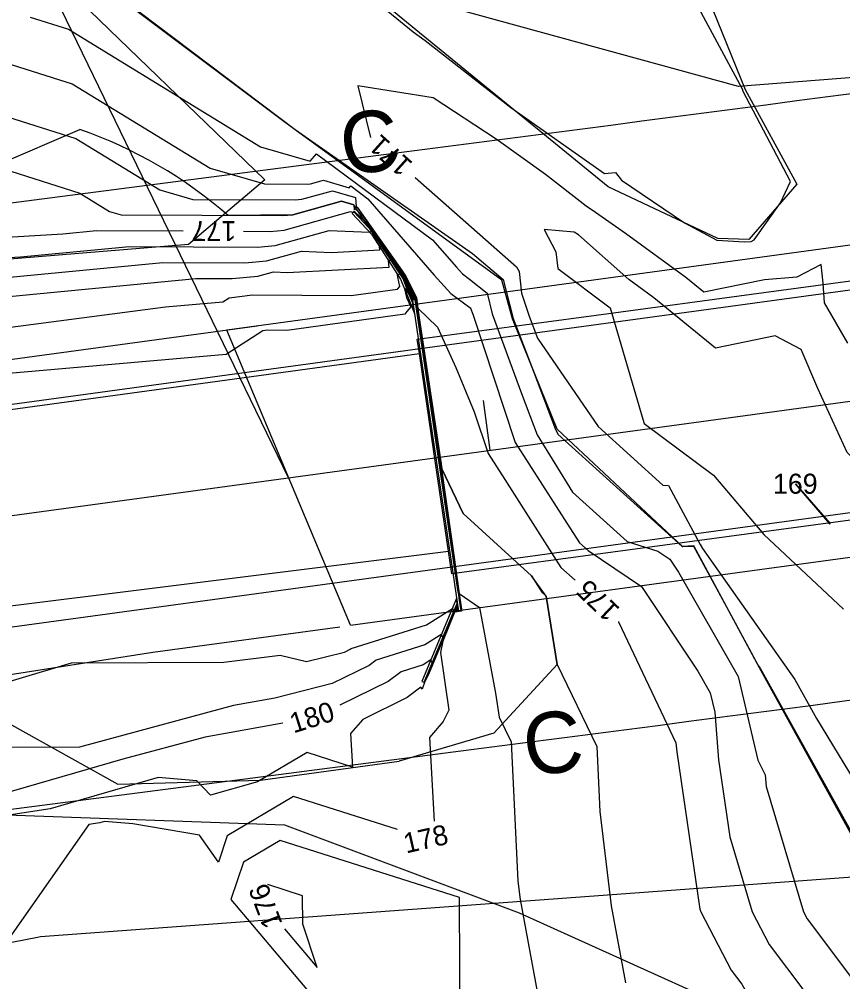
# Model space of a CAD drawing. Extents: x 2086416 to 2115205, y 575507 to 632762.
# Drawn here: x 2111475.2 to 2111557.3, y 581597.8 to 581693.8 of the extents above; entities that cross this region are included whole.
import ezdxf

# ---------------------------------------------------------------- set-up
doc = ezdxf.new("R2010")
doc.units = 0
for name, color, linetype in [('DTM Contours Major', 7, 'Continuous'), ('DTM Contours Major Text', 7, 'Continuous'), ('DTM Contours Minor', 7, 'Continuous'), ('DTM Contours Minor Text', 7, 'Continuous'), ('Exist Hydro Stream or Body of Water', 7, 'Continuous'), ('Exist Hydrographic FEMA Cross Section', 7, 'Continuous'), ('Exist Right of Way Line', 7, 'Continuous'), ('Exist Roads EOP', 7, 'Continuous'), ('Exist Structure Major Bridge WW', 7, 'Continuous'), ('Exist Structure Major Deck Tunnel Box Culvert', 7, 'Continuous'), ('Exist Vegetation Woods Line', 7, 'Continuous'), ('Prop EOT', 7, 'Continuous'), ('Prop Horizontal Alignment', 7, 'Continuous'), ('Prop Horizontal Alignment Station Label', 7, 'Continuous'), ('Prop Horizontal Alignment Tick Small', 7, 'Continuous'), ('Prop Paved Shoulder', 7, 'Continuous'), ('Prop Roadway Bridge', 7, 'Continuous'), ('Prop SS Cut Line', 7, 'Continuous'), ('Prop SS Cut Text', 7, 'Continuous'), ('Prop SS Fill Line', 7, 'Continuous')]:
    doc.layers.add(name, color=color, linetype=linetype)

msp = doc.modelspace()

# ---------------------------------------------------------------- linework, layer by layer
at = {"layer": 'DTM Contours Major'}
for points in [[(2111467.154, 581686.234), (2111480.824, 581681.896), (2111489.192, 581676.776), (2111492.494, 581675.828), (2111502.699, 581675.773), (2111503.352, 581675.831), (2111506.429, 581676.686), (2111508.704, 581676.004), (2111508.773, 581675.108), (2111508.784, 581675.119), (2111508.875, 581675.036), (2111513.354, 581668.687), (2111513.757, 581668.107), (2111514.768, 581666.071), (2111514.785, 581666.034), (2111514.789, 581666.034), (2111514.946, 581664.979), (2111516.9, 581663.081), (2111518.722, 581659.055), (2111520.566, 581654.612), (2111521.942, 581650.454), (2111523.608, 581647.867), (2111529.184, 581639.091), (2111530.614, 581637.815)], [(2111563.624, 581644.535), (2111557.765, 581650.557), (2111554.83, 581656.943), (2111553.167, 581660.831), (2111550.584, 581662.207), (2111544.629, 581660.993), (2111538.463, 581666.005), (2111535.965, 581667.83), (2111530.949, 581672.288), (2111530.521, 581672.558), (2111527.53, 581672.834), (2111528.703, 581670.603), (2111528.883, 581668.916), (2111534.119, 581665.006), (2111537.381, 581653.906), (2111537.496, 581653.447), (2111544.432, 581648.303), (2111549.461, 581642.401), (2111557.401, 581634.942)], [(2111466.87, 581665.45), (2111492.781, 581667.943), (2111496.417, 581667.924), (2111498.953, 581668.15), (2111500.543, 581668.591), (2111501.91, 581668.535), (2111512.084, 581669.069), (2111512.018, 581669.692), (2111512.151, 581669.76), (2111512.231, 581669.823), (2111513.49, 581668.014), (2111513.7, 581667.591), (2111514.529, 581665.844), (2111514.698, 581665.87), (2111515.075, 581663.328), (2111515.596, 581659.884), (2111518.365, 581641.142), (2111518.823, 581637.868), (2111519.166, 581635.474), (2111519.272, 581634.752), (2111519.14, 581634.732), (2111518.801, 581634.678), (2111518.738, 581635.071), (2111516.9, 581630.641), (2111516.405, 581629.626), (2111516.266, 581629.772), (2111516.238, 581629.874), (2111515.472, 581629.388), (2111513.263, 581628.698), (2111511.967, 581627.718), (2111507.15, 581625.341)], [(2111534.94, 581633.703), (2111534.951, 581633.685), (2111540.685, 581621.595), (2111540.754, 581620.704), (2111543.066, 581605.016), (2111543.152, 581604.727), (2111546.206, 581598.924), (2111547.253, 581597.529), (2111560.711, 581573.535), (2111564.818, 581569.801), (2111569.327, 581557.684), (2111570.482, 581553.108), (2111574.03, 581543.189)], [(2111501.468, 581623.557), (2111493.699, 581622.176), (2111485.498, 581619.952), (2111473.32, 581616.448), (2111470.815, 581616.065), (2111467.705, 581615.666), (2111457.917, 581614.372), (2111451.074, 581613.494), (2111428.1, 581610.449), (2111427.715, 581610.257), (2111423.838, 581609.834), (2111421.598, 581608.92), (2111416.907, 581607.541), (2111403.297, 581606.115)]]:
    msp.add_lwpolyline(points, dxfattribs=at)
at = {"layer": 'DTM Contours Minor'}
for points in [[(2111548.202, 581671.635), (2111548.494, 581671.785), (2111551.099, 581675.474), (2111552.125, 581677.605), (2111547.402, 581686.585), (2111547.314, 581686.835), (2111540.681, 581699.19), (2111538.366, 581697.96), (2111532.615, 581704.586), (2111527.172, 581711.478), (2111524.025, 581707.751), (2111520.624, 581705.975), (2111519.423, 581705.653), (2111518.28, 581706.433), (2111512.749, 581713.857), (2111506.226, 581719.408), (2111495.054, 581731.52), (2111493.494, 581731.308)], [(2111487.549, 581730.496), (2111484.48, 581730.078), (2111485.47, 581727.76), (2111493.951, 581708.988), (2111496.972, 581706.844), (2111514.48, 581692.545), (2111515.668, 581691.692), (2111524.198, 581685.007), (2111533.537, 581678.421), (2111534.653, 581678.496), (2111535.245, 581677.738), (2111541.518, 581673.497), (2111544.744, 581671.757), (2111547.518, 581671.576), (2111548.202, 581671.635)], [(2111486.148, 581695.197), (2111501.555, 581683.631), (2111502.551, 581682.906), (2111502.693, 581682.796), (2111520.383, 581670.408), (2111523.452, 581667.816), (2111524.362, 581664.197), (2111524.453, 581663.922), (2111526.096, 581659.621), (2111528.651, 581652.847), (2111528.944, 581652.371), (2111541.304, 581641.187), (2111541.341, 581641.176), (2111541.352, 581641.177), (2111542.435, 581641.236), (2111542.834, 581640.502), (2111546.363, 581633.993), (2111548.886, 581629.315), (2111549.076, 581629.046), (2111561.223, 581607.233)], [(2111368.765, 581694.561), (2111373.18, 581690.967), (2111376.213, 581688.421), (2111374.988, 581684.477), (2111374.345, 581683.964), (2111375.283, 581682.859), (2111378.114, 581684.026), (2111383.988, 581686.435), (2111393.453, 581684.581), (2111404.868, 581681.588), (2111405.004, 581681.538), (2111416.402, 581676.167), (2111417.82, 581675.764), (2111421.041, 581675.098), (2111426.984, 581674.836), (2111450.574, 581672.799), (2111451.554, 581672.806), (2111457.455, 581672.204), (2111464.428, 581672.63), (2111469.437, 581671.797), (2111479.516, 581672.403), (2111482.882, 581672.727), (2111491.534, 581672.68)], [(2111476.241, 581694.01), (2111480.077, 581692.793), (2111499.229, 581681.074), (2111504.206, 581679.645), (2111504.81, 581680.373), (2111516.403, 581671.803), (2111518.792, 581669.045), (2111519.393, 581668.38), (2111520.086, 581667.875), (2111521.845, 581666.467), (2111522.333, 581664.419), (2111525.28, 581656.47), (2111526.841, 581652.331), (2111530.35, 581646.62), (2111535.812, 581641.677), (2111538.872, 581640.719), (2111540.061, 581639.915), (2111540.925, 581638.611), (2111546.88, 581628.212), (2111548.864, 581619.855), (2111549.576, 581618.418), (2111549.677, 581617.246), (2111553.4, 581604.739), (2111553.764, 581604.049), (2111566.508, 581587.068)], [(2111471.697, 581690.122), (2111480.45, 581687.344), (2111494.211, 581678.925), (2111499.639, 581677.366), (2111503.956, 581677.343), (2111504.232, 581677.368), (2111505.534, 581677.729), (2111508.072, 581676.968), (2111508.234, 581677.164), (2111509.952, 581675.894), (2111516.555, 581668.27), (2111518.215, 581666.433), (2111520.131, 581665.036), (2111520.169, 581665.006), (2111520.179, 581664.962), (2111520.404, 581664.357), (2111524.641, 581651.557), (2111530.11, 581643.065), (2111531.071, 581641.554), (2111531.919, 581640.797), (2111537.24, 581637.201), (2111542.85, 581628.732), (2111544.087, 581626.573), (2111544.545, 581624.642), (2111544.913, 581619.908), (2111546.045, 581612.228), (2111548.276, 581604.733), (2111549.985, 581601.487), (2111557.086, 581592.024)], [(2111557.832, 581661.464), (2111555.517, 581665.512), (2111555.366, 581667.475), (2111555.158, 581669.318), (2111552.728, 581668.071), (2111549.514, 581667.794), (2111543.479, 581666.564), (2111541.674, 581668.031), (2111535.656, 581672.428), (2111532.643, 581674.521), (2111531.716, 581675.137), (2111527.674, 581678.306), (2111522.747, 581681.842), (2111516.457, 581685.95), (2111508.951, 581687.161), (2111510.218, 581682.003)], [(2111474.313, 581678.633), (2111481.198, 581676.448), (2111484.174, 581674.627), (2111485.348, 581674.29), (2111501.443, 581674.203), (2111502.472, 581674.295), (2111507.325, 581675.643), (2111508.552, 581675.275), (2111508.589, 581674.792), (2111508.679, 581674.876), (2111509.4, 581674.214), (2111512.43, 581669.92), (2111513.704, 581668.089), (2111514.554, 581666.375), (2111514.734, 581665.996), (2111514.771, 581666.001), (2111515.788, 581659.146), (2111517.192, 581649.853), (2111517.219, 581649.672), (2111517.321, 581648.942), (2111519.439, 581644.481), (2111526.269, 581638.248), (2111527.298, 581636.629), (2111527.742, 581636.232), (2111528.825, 581629.405), (2111532.774, 581621.227), (2111533.089, 581614.752), (2111534.221, 581605.332), (2111535.648, 581597.663)], [(2111514.671, 581678.008), (2111524.783, 581669.107), (2111525.034, 581668.631), (2111525.265, 581666.455), (2111526.022, 581664.168), (2111526.859, 581661.975), (2111532.924, 581653.146), (2111539.358, 581647.32), (2111539.946, 581647.287), (2111543.107, 581641.379), (2111543.325, 581640.975), (2111552.535, 581627.92), (2111554.709, 581624.016), (2111564.464, 581607.913)], [(2111497.534, 581672.648), (2111500.186, 581672.634), (2111501.592, 581672.759), (2111508.221, 581674.6), (2111508.4, 581674.547), (2111508.405, 581674.476), (2111508.575, 581674.633), (2111509.925, 581673.393), (2111511.505, 581671.153), (2111513.65, 581668.07), (2111514.341, 581666.679), (2111514.683, 581665.958), (2111514.753, 581665.969), (2111515.61, 581660.191), (2111516.793, 581652.361), (2111517.506, 581647.539), (2111518.546, 581640.1), (2111519.06, 581636.514), (2111521.067, 581635.109), (2111522.669, 581626.555), (2111523.048, 581624.166), (2111524.233, 581621.711), (2111524.91, 581607.809), (2111525.132, 581605.961), (2111528.046, 581590.305)], [(2111464.732, 581669.45), (2111475.3, 581670.085), (2111486.182, 581671.132), (2111498.93, 581671.064), (2111500.713, 581671.222), (2111506.079, 581672.713), (2111510.111, 581672.547), (2111510.129, 581672.563), (2111510.308, 581672.702), (2111510.451, 581672.571), (2111510.581, 581672.386), (2111513.597, 581668.051), (2111514.127, 581666.983), (2111514.631, 581665.92), (2111514.734, 581665.936), (2111515.431, 581661.237), (2111516.394, 581654.868), (2111517.792, 581645.407), (2111518.638, 581639.356), (2111519.272, 581634.932), (2111519.301, 581634.737), (2111519.265, 581634.732), (2111518.641, 581634.633), (2111518.631, 581634.695), (2111517.409, 581631.75), (2111517.204, 581630.599), (2111518.04, 581624.855), (2111517.471, 581623.738), (2111516.08, 581622.135), (2111516.553, 581613.779)], [(2111471.085, 581667.768), (2111489.481, 581669.538), (2111497.673, 581669.494), (2111499.833, 581669.686), (2111503.311, 581670.652), (2111506.303, 581670.529), (2111511.15, 581670.783), (2111511.119, 581671.08), (2111511.182, 581671.113), (2111511.324, 581671.223), (2111513.543, 581668.032), (2111513.913, 581667.287), (2111514.58, 581665.882), (2111514.716, 581665.903), (2111515.253, 581662.283), (2111515.995, 581657.376), (2111518.079, 581643.275), (2111518.731, 581638.612), (2111519.219, 581635.203), (2111519.286, 581634.745), (2111519.203, 581634.732), (2111518.721, 581634.656), (2111518.684, 581634.883), (2111516.064, 581628.567), (2111515.605, 581627.625), (2111515.364, 581626.964), (2111515.221, 581627.138), (2111513.863, 581626.111), (2111509.449, 581623.933), (2111508.219, 581622.515), (2111508.407, 581619.183), (2111503.877, 581620.626), (2111498.95, 581617.702), (2111494.253, 581616.382), (2111492.88, 581617.804), (2111489.025, 581618.122), (2111478.259, 581615.024), (2111471.081, 581613.927)], [(2111470.971, 581662.653), (2111489.767, 581665.106), (2111495.482, 581665.607), (2111496.094, 581666.005), (2111498.446, 581666.298), (2111508.265, 581666.219), (2111512.889, 581666.862), (2111513.119, 581667.125), (2111512.943, 581668.065), (2111512.918, 581668.303), (2111513.12, 581668.408), (2111513.139, 581668.423), (2111513.437, 581667.995), (2111513.486, 581667.895), (2111514.477, 581665.806), (2111514.68, 581665.837), (2111514.897, 581664.374), (2111515.196, 581662.392), (2111518.652, 581639.01), (2111518.916, 581637.124), (2111519.113, 581635.746), (2111519.258, 581634.759), (2111519.078, 581634.732), (2111518.882, 581634.701), (2111518.792, 581635.26), (2111517.736, 581632.715), (2111517.451, 581632.131), (2111517.372, 581632.216), (2111517.309, 581632.44), (2111515.626, 581631.372), (2111510.771, 581629.854), (2111510.07, 581629.324), (2111506.387, 581627.507), (2111500.669, 581626.069), (2111496.529, 581625.334), (2111481.177, 581621.169), (2111473.746, 581621.131)], [(2111514.426, 581665.768), (2111514.076, 581666.505), (2111514.07, 581666.377), (2111513.681, 581666.938), (2111513.593, 581666.892), (2111513.813, 581666.05), (2111514.217, 581665.091), (2111513.834, 581664.627), (2111513.623, 581664.386), (2111501.864, 581662.752), (2111499.925, 581662.768), (2111499.461, 581662.71), (2111495.816, 581660.338), (2111473.348, 581658.369), (2111466.15, 581656.804), (2111454.207, 581653.913), (2111447.466, 581651.924), (2111445.759, 581651.927), (2111438.707, 581650.157), (2111428.197, 581645.562), (2111418.247, 581641.471)], [(2111469.917, 581626.437), (2111480.37, 581629.578), (2111495.562, 581629.657), (2111501.182, 581630.34), (2111503.81, 581629.699), (2111507.617, 581630.655), (2111508.174, 581630.93), (2111508.279, 581631.01), (2111515.78, 581633.356), (2111518.381, 581635.005), (2111518.477, 581634.659), (2111518.498, 581634.637), (2111518.572, 581634.788), (2111518.845, 581635.448), (2111518.962, 581634.724), (2111519.015, 581634.732), (2111519.244, 581634.766), (2111519.06, 581636.017), (2111519.008, 581636.38), (2111518.938, 581636.877), (2111514.797, 581664.899), (2111514.718, 581665.42), (2111514.661, 581665.804), (2111514.426, 581665.768)], [(2111552.615, 581647.454), (2111556.02, 581643.513), (2111556.038, 581643.472), (2111556.05, 581643.46), (2111556.069, 581643.416), (2111556.042, 581643.437), (2111556.022, 581643.456), (2111552.615, 581647.454)], [(2111512.897, 581612.943), (2111502.542, 581616.244), (2111495.925, 581612.318), (2111495.047, 581609.681), (2111493.145, 581612.369), (2111486.486, 581613.505), (2111483.671, 581613.737), (2111483.198, 581613.6), (2111482.119, 581613.436), (2111472.626, 581599.987), (2111469.34, 581599.165), (2111466.838, 581596.068), (2111463.884, 581593.537), (2111423.2, 581580.097), (2111421.166, 581578.021), (2111413.921, 581573.833), (2111415.71, 581582.768), (2111413.83, 581586.352), (2111407.094, 581599.119), (2111404.077, 581600.927), (2111385.483, 581590.707), (2111395.032, 581602.545), (2111389.517, 581602.876), (2111380.322, 581601.494)], [(2111519.162, 581591.916), (2111519.094, 581606.16), (2111501.206, 581611.862), (2111497.531, 581609.681), (2111496.289, 581605.952), (2111510.712, 581588.873)], [(2111504.9, 581599.184), (2111503.45, 581603.503), (2111503.436, 581606.342), (2111499.959, 581607.451)], [(2111501.645, 581603.038), (2111504.9, 581599.184)]]:
    msp.add_lwpolyline(points, dxfattribs=at)
at = {"layer": 'Exist Hydro Stream or Body of Water'}
for points in [[(2111571.775, 581696.534), (2111557.095, 581714.198), (2111551.353, 581722.025), (2111533.92, 581727.695), (2111525.554, 581727.773), (2111514.019, 581725.289), (2111507.22, 581720.091), (2111517.385, 581713.698), (2111519.528, 581705.926), (2111524.722, 581706.159), (2111528.702, 581714.798), (2111541.061, 581702.903), (2111547.599, 581686.803), (2111552.73, 581677.358), (2111547.949, 581671.835), (2111544.848, 581671.929), (2111533.907, 581677.08), (2111514.732, 581692.736), (2111494.527, 581709.365), (2111484.151, 581730.439), (2111478.633, 581743.802)], [(2111591.587, 581574.691), (2111583.513, 581582.318), (2111586.645, 581587.276), (2111586.904, 581588.764), (2111586.51, 581589.985), (2111561.568, 581606.344), (2111549.003, 581629.07), (2111542.467, 581641.26), (2111541.348, 581641.183), (2111528.816, 581652.894), (2111524.362, 581663.908), (2111523.315, 581667.748), (2111502.682, 581682.779), (2111481.94, 581698.457), (2111468.579, 581724.282), (2111462.999, 581737.482)]]:
    msp.add_lwpolyline(points, dxfattribs=at)
at = {"layer": 'Exist Hydrographic FEMA Cross Section'}
msp.add_lwpolyline([(2111658.777, 581615.589), (2111477.281, 581602.232), (2111476.99, 581602.175), (2111467.38, 581600.311), (2111457.771, 581598.441), (2111448.167, 581596.571), (2111438.557, 581594.706), (2111428.948, 581592.837), (2111419.344, 581590.967), (2111409.734, 581589.102), (2111400.125, 581587.233), (2111390.521, 581585.363), (2111380.911, 581583.498), (2111371.307, 581581.628), (2111361.698, 581579.759), (2111352.088, 581577.894)], dxfattribs=at)
at = {"layer": 'Exist Right of Way Line'}
for points in [[(2111371.804, 581662.16), (2111512.522, 581680.421)], [(2111379.525, 581602.659), (2111520.243, 581620.919)]]:
    msp.add_lwpolyline(points, dxfattribs=at)
for radius in [24756.937, 24816.937]:
    msp.add_arc((2108326.546, 606231.499), radius, 277.3939111, 277.8562149, dxfattribs=at)
at = {"layer": 'Exist Roads EOP'}
for points in [[(2111417.782, 581647.422), (2111417.782, 581647.422), (2111466.254, 581653.757), (2111515.092, 581660.442), (2111516.542, 581650.631)], [(2111419.52, 581628.553), (2111419.52, 581628.553), (2111468.663, 581634.583), (2111518.005, 581640.729), (2111516.542, 581650.631)]]:
    msp.add_lwpolyline(points, dxfattribs=at)
at = {"layer": 'Exist Structure Major Bridge WW'}
for points in [[(2111514.582, 581664.44), (2111514.435, 581665.473), (2111514.083, 581666.345), (2111513.42, 581667.989), (2111510.498, 581672.497), (2111508.557, 581674.592), (2111508.374, 581674.422), (2111510.3, 581672.343), (2111513.197, 581667.873), (2111513.851, 581666.252), (2111514.582, 581664.44)], [(2111514.655, 581665.792), (2111514.408, 581665.755), (2111518.992, 581634.732), (2111519.239, 581634.769), (2111514.655, 581665.792)], [(2111518.864, 581635.514), (2111518.791, 581635.988), (2111518.239, 581634.666), (2111515.343, 581627.732), (2111515.574, 581627.636), (2111518.47, 581634.57), (2111518.864, 581635.514)]]:
    msp.add_lwpolyline(points, dxfattribs=at)
at = {"layer": 'Exist Structure Major Deck Tunnel Box Culvert'}
msp.add_lwpolyline([(2111518.338, 581638.473), (2111518.005, 581640.729), (2111516.542, 581650.631), (2111515.092, 581660.442), (2111514.879, 581661.883), (2111532.718, 581664.281), (2111549.455, 581666.531), (2111567.238, 581668.922), (2111567.482, 581667.278), (2111568.946, 581657.382), (2111570.384, 581647.665), (2111570.703, 581645.511), (2111552.911, 581643.12), (2111536.107, 581640.862), (2111518.338, 581638.473)], dxfattribs=at)
at = {"layer": 'Exist Vegetation Woods Line'}
for points in [[(2112042.216, 581740.223), (2112007.086, 581741.227), (2111957.142, 581737.865), (2111908.66, 581731.855), (2111808.648, 581718.236), (2111760.407, 581712.702), (2111710.337, 581706.767), (2111661.65, 581697.223), (2111616.664, 581692.442), (2111575.004, 581689.288), (2111546.91, 581687.078), (2111515.04, 581695.859), (2111502.165, 581702.852), (2111491.109, 581719.623), (2111479.278, 581746.112)], [(2111452.102, 581736.219), (2111479.268, 581697.501), (2111499.678, 581677.784), (2111492.037, 581671.336), (2111416.636, 581665.128), (2111367.277, 581660.929), (2111318.174, 581654.198), (2111268.317, 581650.615), (2111220.664, 581649.448), (2111173.288, 581649.119), (2111125.979, 581651.571), (2111078.275, 581655.724), (2111059.793, 581657.645)], [(2111257.868, 581581.404), (2111333.104, 581590.969), (2111406.178, 581600.069), (2111473.936, 581614.42), (2111501.631, 581613.416), (2111525.035, 581604.65), (2111555.787, 581590.729), (2111597.414, 581531.022), (2111635.4, 581485.12), (2111692.38, 581438.808), (2111736.925, 581397.696), (2111757.961, 581379.063)]]:
    msp.add_lwpolyline(points, dxfattribs=at)
at = {"layer": 'Prop EOT'}
for p, q in [((2111430.061, 581649.328), (2112312.029, 581769.688)), ((2111433.036, 581627.53), (2112315.004, 581747.89))]:
    msp.add_line(p, q, dxfattribs=at)
at = {"layer": 'Prop Horizontal Alignment'}
msp.add_line((2111431.548, 581638.429), (2112404.465, 581771.2), dxfattribs=at)
at = {"layer": 'Prop Horizontal Alignment Station Label'}
msp.add_line((2111502.038, 581648.048), (2111433.298, 581789.658), dxfattribs=at)
at = {"layer": 'Prop Horizontal Alignment Tick Small'}
msp.add_line((2111522.151, 581650.793), (2111521.475, 581655.747), dxfattribs=at)
at = {"layer": 'Prop Paved Shoulder'}
for p, q in [((2111498.903, 581663.18), (2111463.748, 581658.382)), ((2111488.488, 581630.64), (2111507.165, 581633.188)), ((2111459.664, 581626.117), (2111488.488, 581630.64))]:
    msp.add_line(p, q, dxfattribs=at)
at = {"layer": 'Prop Roadway Bridge'}
for p, q in [((2111585.034, 581674.934), (2111495.86, 581662.765)), ((2111508.215, 581633.332), (2111495.86, 581662.765)), ((2111508.215, 581633.332), (2111597.389, 581645.501))]:
    msp.add_line(p, q, dxfattribs=at)
at = {"layer": 'Prop SS Cut Line'}
for p, q in [((2111507.325, 581675.643), (2111502.472, 581674.295)), ((2111508.552, 581675.275), (2111507.325, 581675.643)), ((2111514.771, 581666.001), (2111508.552, 581675.275)), ((2111502.472, 581674.295), (2111496.001, 581674.207)), ((2111517.321, 581648.942), (2111514.771, 581666.001)), ((2111519.439, 581644.481), (2111517.321, 581648.942)), ((2111526.269, 581638.248), (2111519.439, 581644.481)), ((2111527.742, 581636.232), (2111526.269, 581638.248)), ((2111528.825, 581629.405), (2111527.742, 581636.232)), ((2111528.825, 581629.405), (2111522.497, 581622.577)), ((2111522.497, 581622.577), (2111513.072, 581619.756))]:
    msp.add_line(p, q, dxfattribs=at)
at = {"layer": 'Prop SS Fill Line'}
for p, q in [((2111419.256, 581656.202), (2111481.214, 581682.795)), ((2111499.224, 581617.866), (2111513.072, 581619.756)), ((2111485.015, 581617.465), (2111499.224, 581617.866))]:
    msp.add_line(p, q, dxfattribs=at)
msp.add_lwpolyline([(2111474.094, 581623.547), (2111485.015, 581617.465)], dxfattribs=at)
msp.add_arc((2111466.549, 581640.517), 44.749, 48.8396, 70.86984, dxfattribs=at)

# ---------------------------------------------------------------- texts
at = {"layer": 'DTM Contours Major Text'}
for s, rotation, p in [('175', 136.44274, (2111535.191, 581634.975)), ('180', 17.43289, (2111502.531, 581622.532))]:
    msp.add_text(s, height=2, rotation=rotation, dxfattribs=at).set_placement(p)
at = {"layer": 'DTM Contours Minor Text'}
for s, rotation, p in [('171', 138.09884, (2111514.528, 581679.441)), ('177', 179.69151, (2111496.815, 581673.652)), ('178', 12.8825, (2111513.76, 581610.55)), ('176', 110.91041, (2111501.456, 581603.561))]:
    msp.add_text(s, height=2, rotation=rotation, dxfattribs=at).set_placement(p)
msp.add_text('169', height=2, dxfattribs=at).set_placement((2111550.355, 581646.454))
at = {"layer": 'Prop SS Cut Text'}
for p in [(2111507.614, 581678.163), (2111525.877, 581618.198)]:
    msp.add_text('C', height=6.104, rotation=7.77101, dxfattribs=at).set_placement(p)

doc.saveas('drawing.dxf')
